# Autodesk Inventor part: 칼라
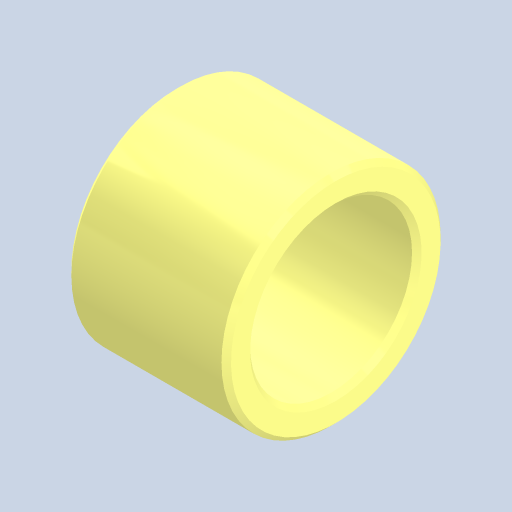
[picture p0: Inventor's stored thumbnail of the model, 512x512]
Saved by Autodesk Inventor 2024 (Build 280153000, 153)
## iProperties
Created: 2026-01
Part Number: 칼라
Material: 강철, 연강
Document SubType Name: Modeling
Designer: 2-10
Density: 7.85 g/cm^3
Appearance: 기본값
Author: jhkim
Sending System: Autodesk Inventor 2026
Preprocessor: ST-DEVELOPER v20.1
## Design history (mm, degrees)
feature "솔리드1"
node "솔리드2"
